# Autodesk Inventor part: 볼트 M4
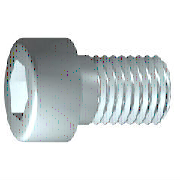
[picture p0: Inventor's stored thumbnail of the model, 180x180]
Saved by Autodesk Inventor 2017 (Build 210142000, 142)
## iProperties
IsCustomPart: 0
Created: 2015-12
Part Number: 볼트 M4
Material: 강철, 연강
Description: 6각머리 태핑 나사
Document SubType Name: Modeling
Standard: KS B 1003
Designer: mdu
Standards Organization: KS
Language: ko-KR
Size Designation: M 4 x 12
Categories: <MemberInstance><Categories><Category DisplayName="조임쇠" InternalName="e4da775c-781d-43d5-af7c-5136215cf5a6" Mnemonic="FSTN"><Category DisplayName="볼트" InternalN
Density: 7.86 g/cm^3
Appearance: 강철
Mass: 2.23465 g
Surface Area: 3.30853 cm^2
Volume: 0.284306 cm^3
Author: mdu
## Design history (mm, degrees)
sketch "스케치1"
  geometry: L1 (-1, 0)-(12, 0); L2 (12, 0)-(12, 2); L3 (12, 2)-(1.75, 2); L4 (1.75, 2)-(1.32, 2); L5 (1.32, 2)-(0, 2); L6 (0, 2)-(0, 3.5); L7 (0, 3.5)-(-4, 3.5); L8 (-4, 3.5)-(-4, 1.732); L9 (-4, 1.732)-(-2, 1.732); L10 (-2, 1.732)-(-1, 0); L11 (-7.2, 0)-(15.2, 0) reference; L12 (0, -0.7)-(0, 4.2) reference; L13 (1.75, 2)-(0, 2)
  constraints: 22 end point, 6 parallel, 2 collinear, 2 perpendicular, 1 horizontal, 1 point on line
  dimensions: "d1" = 10.25 distance from line of L3.end L2 (= GEL); "d2" = 0.42952 distance of L4.end L3.end (computed from GAL); "d3" = 4 distance between parallel lines of L8 L6 (= KOH); "d4" = 2 distance of L8.end L9.end (= INTI); "d5" = 60 deg angle of L10 L1; "d6" = 4 diameter of L3 L1 (= GD); "d7" = 4 diameter of L5 L1 (= BDM); "d8" = 3.4641 diameter of L9 L1 (= 1.1547 x SW); "d9" = 7 diameter of L7 L1 (= KOD); "d26" = 12 distance between parallel lines of L12 L2 (= NLG)
revolve "본체" sketch "스케치1" stored, may be unused: angle "d10" = 90 deg
sketch "스케치2"
  geometry: L1 (0, -4.9)-(0, 4.9) reference; L2 (-4.9, 0)-(4.9, 0) reference; L3 (1.732, 0)-(0.866, -1.5); L4 (0.866, -1.5)-(-0.866, -1.5); L5 (-0.866, -1.5)-(-1.732, 0); L6 (-1.732, 0)-(-0.866, 1.5); L7 (-0.866, 1.5)-(0.866, 1.5); L8 (0.866, 1.5)-(1.732, 0); 2 further points
  constraints: 12 end point, 1 coincident, 1 horizontal alignment, 1 point on line, 12 other
extrude "슬롯" join sketch "스케치2" stored distance "d11" = 10; taper "d12" = 0 deg
workplane "Work Plane1"
fillet "Fillet2" dims "d30" = 0.1 (= R)
body "Solid1"
fillet "모깎기1" dims "d17" = 0.4 (= RR)
feature "스레드" dims "d13" = 10.25 (= GEL), "d14" = 0
chamfer "모따기1" distance "d15" = 0.42941 (= -0.5 x SPD + 0.5 x GD); stored, may be unused: second distance "d16" = 0.42941 (= GUL), angle "d27" = 45 deg
other parameters: "GD" = 4 (= NND) [user parameter; used in 2 equation terms], "NLG" = 12 [user parameter; used in 1 equation term], "GEL" = 10.25 [user parameter; used in 2 equation terms], "KOD" = 7 [user parameter; used in 1 equation term], "KOH" = 4 [user parameter; used in 1 equation term], "INTI" = 2 [user parameter; used in 1 equation term], "GAL" = 0.42941 (= 0.61345 x PTC) [user parameter; used in 1 equation term], "GUL" = 0.42941 (= 0.61345 x PTC) [user parameter; used in 1 equation term], "BDM" = 4 (= NND) [user parameter; used in 1 equation term], "SW" = 3 [user parameter; used in 2 equation terms], "RR" = 0.4 [user parameter; used in 1 equation term], "SPD" = 3.14117 (= NND - 1.2269 x PTC) [user parameter; used in 1 equation term], "d19" = 0, "d28" = 0, "d29" = 0, "R" = 0.1 [user parameter; used in 1 equation term], "PHH" = 0.2 [user parameter], "GD1" = 3.14117 (= THREADDIA - 1.2269 x PTC) [user parameter], "THREADDIA" = 4 [user parameter; used in 1 equation term], "FAWI" = 45 deg [user parameter], "TPU" = 14.28571 (computed from PTC) [user parameter], "PTC" = 0.7 [user parameter; used in 5 equation terms], "NND" = 4 [user parameter; used in 3 equation terms], "TOA" = 30 deg [user parameter], "E0" = 3.465 (= 1.155 x SW) [user parameter]
